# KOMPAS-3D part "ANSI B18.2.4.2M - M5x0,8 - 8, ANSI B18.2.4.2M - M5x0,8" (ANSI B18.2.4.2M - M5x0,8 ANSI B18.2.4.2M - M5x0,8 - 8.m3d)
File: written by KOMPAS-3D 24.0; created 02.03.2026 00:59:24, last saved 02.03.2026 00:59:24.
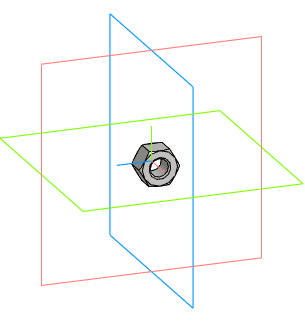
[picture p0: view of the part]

Document properties: Автор: R2D2; Полное имя файла: E:\Работа\Зайцев\GVWR3131M-2W-F-S Задвижка клиновая с выдвижным штоком DN.ru Ду50-200 Ру63\DN100\исходные материалы\ANSI B18.2.4.2M - M5x0,8 ANSI B18.2.4.2M - M5x0,8 - 8.m3d

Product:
- Body: Solid1  | qty 1
- Part/product: ANSI B18.2.4.2M - M5x0,8 - 8  | designation ANSI B18.2.4.2M - M5x0,8
    Комментарий: Типы метрических   шестигранных гаек   2
    additional columns: Сталь, мягкая

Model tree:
1. Solid1  (labels: Solid1)

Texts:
  ANSI B18.2.4.2M - M5x0,8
